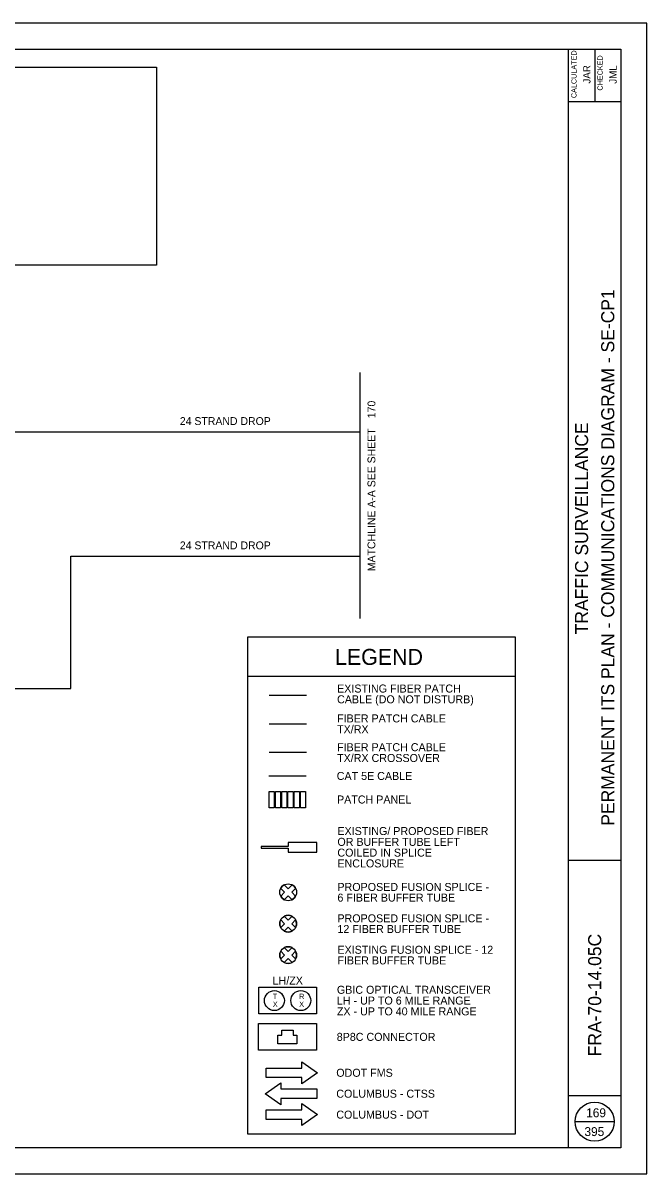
# Model space of a CAD drawing. Extents: x 1805893 to 1833564, y 708898 to 716199.
# Drawn here: x 1831763.9 to 1832002.5, y 713757.9 to 714197.9 of the extents above; entities that cross this region are included whole.
import ezdxf

# ---------------------------------------------------------------- set-up
doc = ezdxf.new("R2010")
doc.units = 0
for name, color, linetype in [('BR_P_Sub_Hidden', 7, 'Continuous'), ('BR_X_Slab_Object', 7, 'Continuous'), ('SH_Border', 7, 'Continuous'), ('SH_Cut_Line', 7, 'Continuous'), ('SH_Data', 7, 'Continuous')]:
    doc.layers.add(name, color=color, linetype=linetype)

msp = doc.modelspace()

# ---------------------------------------------------------------- linework, layer by layer
at = {"layer": 'BR_P_Sub_Hidden'}
msp.add_lwpolyline([(1831501.65, 713935.11), (1831390.73, 713935.11), (1831390.73, 714181.08), (1831814.91, 714181.08), (1831814.91, 714105.3), (1831725.63, 714105.3), (1831725.63, 713875.12), (1831501.65, 713875.12)], close=True, dxfattribs=at)
at = {"layer": 'SH_Border'}
for p, q in [((1831972.49, 713767.91), (1831972.49, 714187.91)), ((1831982.49, 714187.91), (1831982.49, 714167.91)), ((1831972.49, 714167.91), (1831992.49, 714167.91)), ((1831972.49, 713877.91), (1831992.49, 713877.91)), ((1831972.49, 713787.91), (1831992.49, 713787.91))]:
    msp.add_line(p, q, dxfattribs=at)
msp.add_lwpolyline([(1831362.49, 714187.91), (1831992.49, 714187.91), (1831992.49, 713767.91), (1831362.49, 713767.91)], close=True, dxfattribs=at)
at = {"layer": 'SH_Cut_Line'}
msp.add_lwpolyline([(1831322.49, 713757.91), (1832002.49, 713757.91), (1832002.49, 714197.91), (1831322.49, 714197.91)], close=True, dxfattribs=at)
at = {"layer": 'SH_Data'}
for p, q in [((1831892.88, 713970.24), (1831892.88, 714064.37)), ((1831677.88, 714041.63), (1831892.88, 714041.63)), ((1831782.23, 713943.53), (1831782.23, 713994.15)), ((1831782.23, 713994.15), (1831892.88, 713994.15)), ((1831677.88, 713943.53), (1831782.23, 713943.53)), ((1831857.98, 713941.01), (1831872.32, 713941.01)), ((1831857.98, 713930.01), (1831872.32, 713930.01)), ((1831863.92, 713865.61), (1831862.43, 713867.1)), ((1831862.43, 713867.1), (1831863.92, 713865.61)), ((1831862.43, 713864.11), (1831863.92, 713865.61)), ((1831863.92, 713865.61), (1831862.43, 713864.11)), ((1831865.28, 713866.96), (1831863.79, 713868.45)), ((1831865.28, 713866.96), (1831863.79, 713868.45)), ((1831865.28, 713866.96), (1831866.77, 713868.45)), ((1831866.77, 713868.45), (1831865.28, 713866.96)), ((1831866.63, 713865.61), (1831868.13, 713867.1)), ((1831866.63, 713865.61), (1831868.13, 713867.1)), ((1831868.13, 713864.11), (1831866.63, 713865.61)), ((1831868.13, 713864.11), (1831866.63, 713865.61)), ((1831863.79, 713862.76), (1831865.28, 713864.25)), ((1831863.79, 713862.76), (1831865.28, 713864.25)), ((1831866.77, 713862.76), (1831865.28, 713864.25)), ((1831865.28, 713864.25), (1831866.77, 713862.76)), ((1831865.28, 713854.95), (1831863.79, 713856.44)), ((1831863.79, 713856.44), (1831865.28, 713854.95)), ((1831865.28, 713854.95), (1831866.77, 713856.44)), ((1831865.28, 713854.95), (1831866.77, 713856.44)), ((1831863.92, 713853.6), (1831862.43, 713855.09)), ((1831863.92, 713853.6), (1831862.43, 713855.09)), ((1831862.43, 713852.1), (1831863.92, 713853.6)), ((1831862.43, 713852.1), (1831863.92, 713853.6)), ((1831863.79, 713850.75), (1831865.28, 713852.24)), ((1831865.28, 713852.24), (1831863.79, 713850.75)), ((1831866.77, 713850.75), (1831865.28, 713852.24)), ((1831866.77, 713850.75), (1831865.28, 713852.24)), ((1831866.63, 713853.6), (1831868.13, 713855.09)), ((1831868.13, 713855.09), (1831866.63, 713853.6)), ((1831868.13, 713852.1), (1831866.63, 713853.6)), ((1831866.63, 713853.6), (1831868.13, 713852.1)), ((1831863.92, 713841.59), (1831862.43, 713843.08)), ((1831863.92, 713841.59), (1831862.43, 713843.08)), ((1831865.28, 713842.95), (1831863.79, 713844.44)), ((1831863.79, 713844.44), (1831865.28, 713842.95)), ((1831865.28, 713842.95), (1831866.77, 713844.44)), ((1831865.28, 713842.95), (1831866.77, 713844.44)), ((1831866.63, 713841.59), (1831868.13, 713843.08)), ((1831868.13, 713843.08), (1831866.63, 713841.59)), ((1831862.43, 713840.1), (1831863.92, 713841.59)), ((1831862.43, 713840.1), (1831863.92, 713841.59)), ((1831863.79, 713838.74), (1831865.28, 713840.24)), ((1831865.28, 713840.24), (1831863.79, 713838.74)), ((1831866.77, 713838.74), (1831865.28, 713840.24)), ((1831866.77, 713838.74), (1831865.28, 713840.24)), ((1831868.13, 713840.1), (1831866.63, 713841.59)), ((1831866.63, 713841.59), (1831868.13, 713840.1)), ((1831870.56, 713798.4), (1831870.56, 713800.8)), ((1831856.82, 713798.4), (1831870.56, 713798.4)), ((1831856.82, 713794.8), (1831856.82, 713798.4)), ((1831870.56, 713794.8), (1831856.82, 713794.8)), ((1831870.56, 713792.4), (1831870.56, 713794.8)), ((1831862.49, 713792.8), (1831862.49, 713790.4)), ((1831862.49, 713790.4), (1831876.22, 713790.4)), ((1831876.22, 713790.4), (1831876.22, 713786.8)), ((1831876.22, 713786.8), (1831862.49, 713786.8)), ((1831862.49, 713786.8), (1831862.49, 713784.4)), ((1831856.82, 713782.4), (1831870.56, 713782.4)), ((1831856.82, 713778.8), (1831856.82, 713782.4)), ((1831870.56, 713782.4), (1831870.56, 713784.8)), ((1831870.56, 713778.8), (1831856.82, 713778.8)), ((1831870.56, 713776.4), (1831870.56, 713778.8)), ((1831974.99, 713777.91), (1831989.99, 713777.91))]:
    msp.add_line(p, q, dxfattribs=at)
for points in [[(1831849.81, 713963.24), (1831952.04, 713963.24), (1831952.04, 713948.13), (1831849.81, 713948.13)], [(1831952.04, 713963.24), (1831952.04, 713773.07), (1831849.81, 713773.07), (1831849.81, 713963.24)], [(1831859.98, 713904.19), (1831859.98, 713897.94), (1831858.02, 713897.94), (1831858.02, 713904.19)], [(1831862.38, 713904.19), (1831862.38, 713897.94), (1831860.42, 713897.94), (1831860.42, 713904.19)], [(1831864.78, 713904.19), (1831864.78, 713897.94), (1831862.81, 713897.94), (1831862.81, 713904.19)], [(1831867.17, 713904.19), (1831867.17, 713897.94), (1831865.21, 713897.94), (1831865.21, 713904.19)], [(1831869.57, 713904.19), (1831869.57, 713897.94), (1831867.6, 713897.94), (1831867.6, 713904.19)], [(1831871.96, 713904.19), (1831871.96, 713897.94), (1831870, 713897.94), (1831870, 713904.19)], [(1831854.02, 713829.33), (1831876.12, 713829.33), (1831876.12, 713819.08), (1831854.02, 713819.08)], [(1831853.97, 713815.45), (1831876.06, 713815.45), (1831876.06, 713805.2), (1831853.97, 713805.2)]]:
    msp.add_lwpolyline(points, close=True, dxfattribs=at)
for points in [[(1831872.35, 713919.01), (1831857.98, 713919.01), (1831857.98, 713919.01), (1831857.98, 713919.01)], [(1831857.84, 713910.07), (1831872.18, 713910.1), (1831872.18, 713910.1)], [(1831854.98, 713883.13), (1831854.98, 713882.82), (1831854.98, 713882.52), (1831865.27, 713882.52), (1831865.27, 713880.99), (1831876.31, 713880.99), (1831876.31, 713884.66), (1831865.27, 713884.66), (1831865.27, 713883.13), (1831854.98, 713883.13)], [(1831876.31, 713880.99), (1831876.31, 713884.66), (1831865.27, 713884.66), (1831865.27, 713883.13), (1831854.98, 713883.13), (1831854.98, 713882.82), (1831854.98, 713882.52), (1831865.27, 713882.52), (1831865.27, 713880.99), (1831876.31, 713880.99)], [(1831862.89, 713810.93), (1831862.89, 713812.84), (1831867.14, 713812.84), (1831867.14, 713810.93)], [(1831867.14, 713810.93), (1831868.65, 713810.93), (1831868.65, 713807.7), (1831861.38, 713807.7), (1831861.38, 713810.93), (1831862.89, 713810.93)], [(1831870.56, 713800.8), (1831876.56, 713796.6), (1831870.56, 713792.4)], [(1831862.49, 713784.4), (1831856.49, 713788.6), (1831862.49, 713792.8)], [(1831870.56, 713784.8), (1831876.56, 713780.6), (1831870.56, 713776.4)]]:
    msp.add_lwpolyline(points, dxfattribs=at)
for centre, radius in [((1831865.28, 713865.61), 3.22), ((1831865.28, 713853.6), 3.22), ((1831865.28, 713841.59), 3.22), ((1831860.02, 713824.2), 3.81), ((1831870.12, 713824.2), 3.81), ((1831982.49, 713777.91), 7.5)]:
    msp.add_circle(centre, radius, dxfattribs=at)
for centre, start, end in [((1831865.28, 713865.61), 117.647, 152.353), ((1831865.28, 713865.61), 27.647, 62.353), ((1831865.28, 713865.61), 207.647, 242.353), ((1831865.28, 713865.61), 297.647, 332.353), ((1831865.28, 713853.6), 62.353, 117.647), ((1831865.28, 713853.6), 152.353, 207.647), ((1831865.28, 713853.6), 332.353, 27.647), ((1831865.28, 713853.6), 242.353, 297.647), ((1831865.28, 713841.59), 152.353, 207.647), ((1831865.28, 713841.59), 62.353, 117.647), ((1831865.28, 713841.59), 332.353, 27.647), ((1831865.28, 713841.59), 242.353, 297.647)]:
    msp.add_arc(centre, 3.22, start, end, dxfattribs=at)

# ---------------------------------------------------------------- texts
at = {"layer": 'BR_X_Slab_Object'}
for s, height, rotation, p in [('170', 3, 90, (1831898.63, 714046.83)), ('T', 2, 0.0475, (1831859.42, 713824.8)), ('R', 2, 0.0475, (1831869.51, 713824.8)), ('X', 2, 0.0475, (1831859.42, 713821.8)), ('X', 2, 0.0475, (1831869.51, 713821.8))]:
    msp.add_text(s, height=height, rotation=rotation, dxfattribs=at).set_placement(p)
at = {"layer": 'SH_Data'}
for s, height, rotation, p in [('CALCULATED', 2, 90, (1831975.54, 714169.2)), ('JAR', 2.8, 90, (1831980.89, 714174.74)), ('CHECKED', 2, 90, (1831985.54, 714172.07)), ('JML', 2.8, 90, (1831990.89, 714174.7)), ('PERMANENT ITS PLAN - COMMUNICATIONS DIAGRAM - SE-CP1', 5, 90, (1831989.99, 713891.04)), ('24 STRAND DROP', 3, 360, (1831823.86, 714044.24)), ('MATCHLINE A-A SEE SHEET', 3, 90, (1831898.63, 713988.34)), ('TRAFFIC SURVEILLANCE', 5, 90, (1831979.99, 713964.23)), ('24 STRAND DROP', 3, 360, (1831823.86, 713996.72)), ('FRA-70-14.05C', 5, 90, (1831984.99, 713802.9))]:
    msp.add_text(s, height=height, rotation=rotation, dxfattribs=at).set_placement(p)
for s, height, p in [('LEGEND', 6.119, (1831883.19, 713952.52)), ('EXISTING FIBER PATCH ', 3.0596, (1831883.99, 713941.96)), ('CABLE (DO NOT DISTURB)', 3.0596, (1831883.99, 713937.84)), ('FIBER PATCH CABLE', 3.0596, (1831883.99, 713930.54)), ('TX/RX', 3.06, (1831883.99, 713926.42)), ('FIBER PATCH CABLE', 3.0596, (1831883.99, 713919.54)), ('TX/RX CROSSOVER', 3.0596, (1831883.99, 713915.41)), ('CAT 5E CABLE', 3.0596, (1831883.86, 713908.54)), ('PATCH PANEL', 3.0596, (1831883.97, 713899.54)), ('EXISTING/ PROPOSED FIBER ', 3.0596, (1831884.11, 713887.48)), ('OR BUFFER TUBE LEFT ', 3.0596, (1831884.11, 713883.35)), ('COILED IN SPLICE ', 3.0596, (1831884.11, 713879.23)), ('ENCLOSURE', 3.06, (1831884.11, 713875.11)), ('PROPOSED FUSION SPLICE - ', 3.0596, (1831884.12, 713866.11)), ('6 FIBER BUFFER TUBE', 3.0596, (1831884.12, 713862.03)), ('PROPOSED FUSION SPLICE - ', 3.0596, (1831884.12, 713854.11)), ('12 FIBER BUFFER TUBE', 3.0596, (1831884.12, 713850.03)), ('EXISTING FUSION SPLICE - 12 ', 3.0596, (1831884.12, 713842.1)), ('FIBER BUFFER TUBE', 3.0596, (1831884.12, 713838.03)), ('LH/ZX', 3.06, (1831859.34, 713830.33)), ('GBIC OPTICAL TRANSCEIVER', 3.0596, (1831883.92, 713826.8)), ('LH - UP TO 6 MILE RANGE', 3.0596, (1831883.92, 713822.67)), ('ZX - UP TO 40 MILE RANGE', 3.0596, (1831883.92, 713818.55)), ('8P8C CONNECTOR', 3.0596, (1831883.86, 713808.8)), ('ODOT FMS', 3.06, (1831883.69, 713795.07)), ('COLUMBUS - CTSS', 3.0596, (1831883.69, 713787.07)), ('COLUMBUS - DOT', 3.0596, (1831883.69, 713779.07)), ('169', 3.4, (1831979.23, 713779.61)), ('395', 3.4, (1831978.57, 713772.41))]:
    msp.add_text(s, height=height, dxfattribs=at).set_placement(p)

doc.saveas('drawing.dxf')
